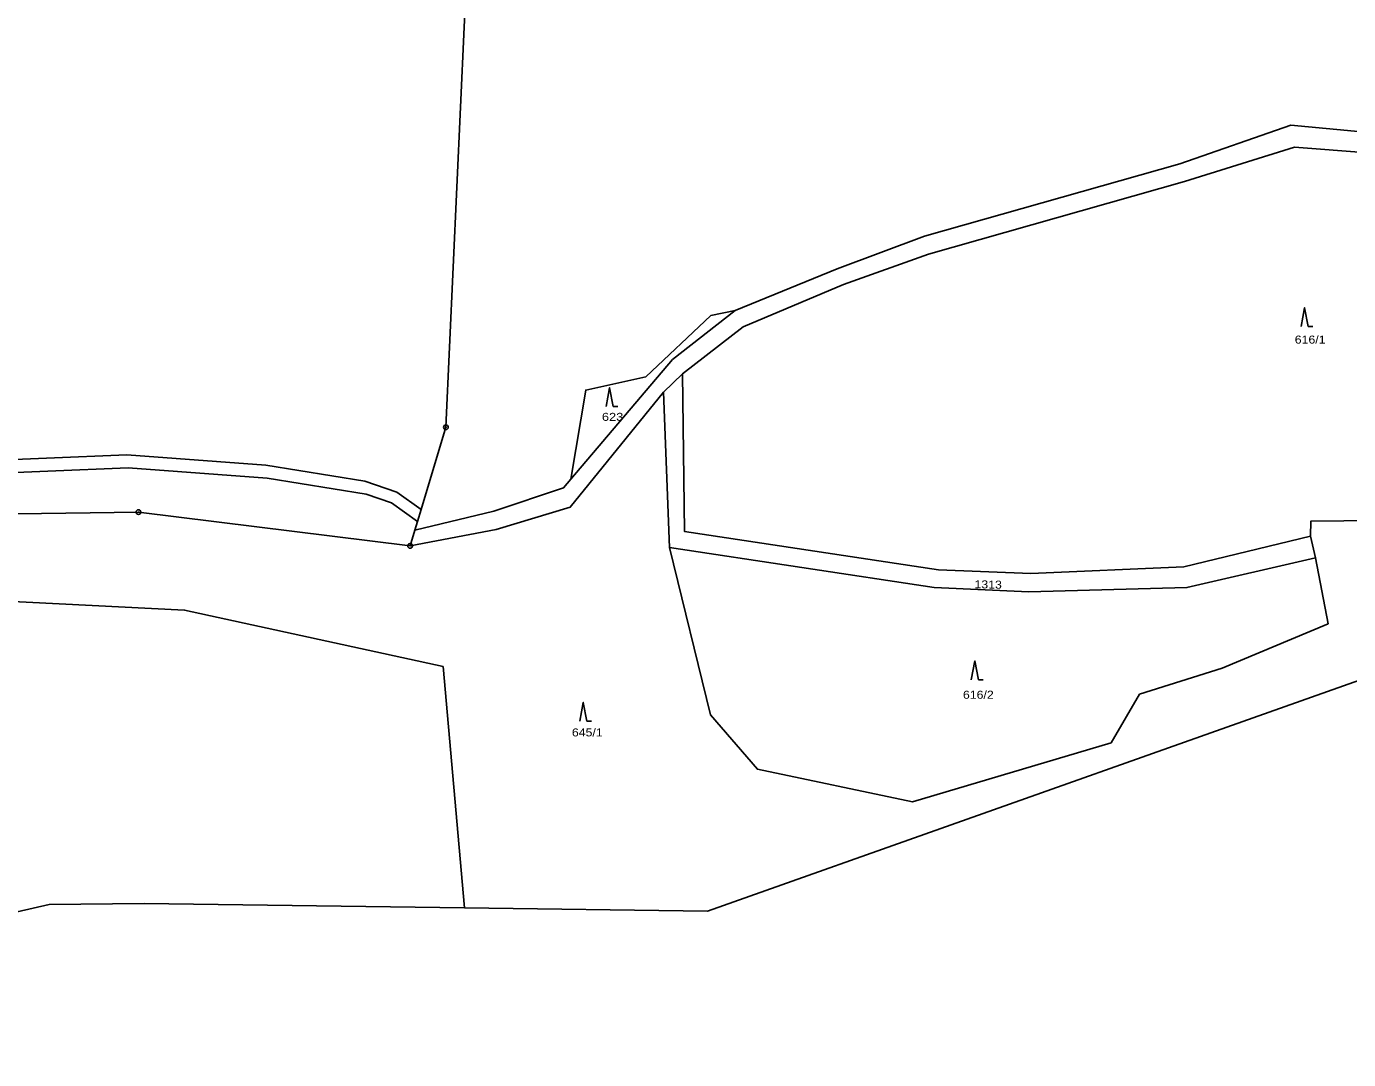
# Model space of a CAD drawing. Extents: x -872229 to -869198, y -1075981 to -1074329.
# Drawn here: x -870040 to -869759.2, y -1075751.2 to -1075531.8 of the extents above; entities that cross this region are included whole.
import ezdxf

# ---------------------------------------------------------------- set-up
doc = ezdxf.new("R2010")
doc.units = 0
doc.header["$LTSCALE"] = 0.68
for name, color, linetype, lineweight in [('1', 7, 'Continuous', 25), ('3', 7, 'Continuous', 25), ('8', 7, 'Continuous', 25)]:
    doc.layers.add(name, color=color, linetype=linetype, lineweight=lineweight)
doc.layers.add('2', color=7, linetype='Continuous')

msp = doc.modelspace()

# ---------------------------------------------------------------- linework, layer by layer
at = {"layer": '1'}
for p, q in [((-870015.01, -1075718.11), (-869946.97, -1075719.04)), ((-869946.97, -1075719.04), (-869895.39, -1075719.74))]:
    msp.add_line(p, q, dxfattribs=at)
for points in [[(-869956.21, -1075634.42), (-869950.93, -1075616.94), (-869945.48, -1075497.93), (-869942.3, -1075409.15)], [(-869889.5, -1075592.13), (-869867.84, -1075583.27), (-869849.28, -1075576.32), (-869795.03, -1075560.97), (-869771.51, -1075552.75), (-869740.67, -1075555.67), (-869710.85, -1075550.74), (-869675.12, -1075544), (-869656.72, -1075536.14)], [(-869657.44, -1075540.59), (-869674.12, -1075547.66), (-869710.28, -1075554.3), (-869740.46, -1075559.8), (-869770.69, -1075557.44), (-869794.04, -1075564.75), (-869848.43, -1075580.14), (-869866.49, -1075586.59), (-869887.81, -1075595.64), (-869900.72, -1075605.56)], [(-870360.91, -1075564.7), (-870334.21, -1075571.6), (-870312.37, -1075586.81), (-870293.77, -1075595.76), (-870270.86, -1075602.02), (-870243.34, -1075610.77), (-870217.09, -1075618.71), (-870179.15, -1075630.08), (-870157.97, -1075632.03), (-870128.13, -1075632.63), (-870114.57, -1075631.72), (-870098.39, -1075625.25), (-870092.04, -1075619.77), (-870087.29, -1075619.63), (-870052.6, -1075626.97), (-870018.4, -1075625.53), (-869988.87, -1075627.77), (-869967.84, -1075631.16), (-869962.49, -1075632.97), (-869956.97, -1075636.94), (-869956.21, -1075634.42)], [(-869956.21, -1075634.42), (-869961.39, -1075630.69), (-869968.14, -1075628.41), (-869989.17, -1075625.02), (-870018.7, -1075622.78), (-870052.9, -1075624.22), (-870087.59, -1075616.88), (-870093.16, -1075617.33), (-870100.3, -1075623.21), (-870115.61, -1075629.33), (-870126.17, -1075630.04), (-870156.01, -1075629.44), (-870177.19, -1075627.49), (-870215.13, -1075616.12), (-870241.38, -1075608.18), (-870268.9, -1075599.43), (-870291.81, -1075593.17), (-870310.41, -1075584.22), (-870332.25, -1075569.01)], [(-870319.49, -1075589.3), (-870295.19, -1075603.73), (-870207.28, -1075631.27), (-870168.61, -1075639.64), (-870121.56, -1075638.1), (-870072.83, -1075635.74), (-870016.23, -1075634.96), (-869958.54, -1075642.14), (-869957.53, -1075638.79), (-869956.97, -1075636.94)], [(-869924.37, -1075627.94), (-869902.8, -1075602.53), (-869889.5, -1075592.13)], [(-869924.37, -1075627.94), (-869921.22, -1075609.04), (-869908.51, -1075606.2), (-869894.67, -1075593.21), (-869889.5, -1075592.13)], [(-869946.97, -1075719.04), (-869951.52, -1075667.78), (-870006.44, -1075655.77), (-870192.84, -1075646.38), (-870362.26, -1075599.45), (-870356.17, -1075620.52)], [(-869767.28, -1075640.08), (-869794.22, -1075646.61), (-869826.72, -1075648), (-869846.35, -1075647.25), (-869900.26, -1075639.11), (-869900.72, -1075605.56), (-869904.69, -1075609.48), (-869903.45, -1075642.46)], [(-869904.69, -1075609.48), (-869924.54, -1075633.93), (-869940.24, -1075638.66), (-869958.54, -1075642.14)], [(-869957.53, -1075638.79), (-869940.75, -1075634.78), (-869925.94, -1075629.8), (-869924.37, -1075627.94)], [(-869895.39, -1075719.74), (-869729.92, -1075661.11), (-869666.68, -1075657.35), (-869593.09, -1075655.24), (-869520.45, -1075655.26), (-869463.49, -1075641.67), (-869392.24, -1075631.04), (-869390.16, -1075631.43)], [(-869767.28, -1075640.08), (-869767.22, -1075636.85), (-869725.35, -1075636.46), (-869675.65, -1075632.94)], [(-869903.45, -1075642.46), (-869847.25, -1075650.97), (-869827.1, -1075651.9), (-869793.57, -1075650.99), (-869766.26, -1075644.69), (-869767.28, -1075640.08)], [(-869903.45, -1075642.46), (-869894.75, -1075678.04), (-869884.79, -1075689.57), (-869851.82, -1075696.48), (-869809.65, -1075683.99), (-869803.62, -1075673.66), (-869786.07, -1075668.09), (-869763.58, -1075658.67), (-869766.26, -1075644.69)], [(-870179.01, -1075751.24), (-870035.17, -1075718.28), (-870015.01, -1075718.11)]]:
    msp.add_lwpolyline(points, dxfattribs=at)
at = {"layer": '3'}
for p, q in [((-869767.82, -1075595.55), (-869766.824, -1075595.55)), ((-869915.41, -1075612.55), (-869914.414, -1075612.55)), ((-869837.85, -1075670.58), (-869836.854, -1075670.58)), ((-869921.01, -1075679.37), (-869920.014, -1075679.37))]:
    msp.add_line(p, q, dxfattribs=at)
for points in [[(-869767.82, -1075595.55), (-869768.57, -1075591.55), (-869769.32, -1075595.55)], [(-869915.41, -1075612.55), (-869916.16, -1075608.55), (-869916.91, -1075612.55)], [(-869837.85, -1075670.58), (-869838.6, -1075666.58), (-869839.35, -1075670.58)], [(-869921.01, -1075679.37), (-869921.76, -1075675.37), (-869922.51, -1075679.37)]]:
    msp.add_lwpolyline(points, dxfattribs=at)
at = {"layer": '8'}
for centre, radius in [((-869950.93, -1075616.9399), 0.5), ((-869950.93, -1075616.9399), 0.0303), ((-870016.23, -1075634.9599), 0.5), ((-870016.23, -1075634.9599), 0.0303), ((-869958.54, -1075642.1399), 0.5), ((-869958.54, -1075642.1399), 0.0303)]:
    msp.add_circle(centre, radius, dxfattribs=at)

# ---------------------------------------------------------------- texts
at = {"layer": '2'}
for s, width, p in [('616/1', 1.15, (-869770.66, -1075599.17)), ('623', 1.2, (-869917.81, -1075615.58)), ('616/2', 1.15, (-869841.13, -1075674.6)), ('645/1', 1.15, (-869924.18, -1075682.6))]:
    msp.add_text(s, height=1.7, dxfattribs=dict(at, width=width)).set_placement(p)
at = {"layer": '2', "width": 1.15}
msp.add_text('1313', height=1.7, rotation=359, dxfattribs=at).set_placement((-869838.694, -1075651.129))

doc.saveas('drawing.dxf')
